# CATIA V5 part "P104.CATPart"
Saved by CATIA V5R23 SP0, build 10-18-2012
Part number: P104
Definition: Tendeur
Bounding box of the stored display mesh (mm): x -4 to 4, y -17 to 17, z -16.952 to 16.952
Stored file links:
  C:\wamp\www\COURS\CONCEPTION GMP1\TITRE 02-SEMESTRE 2\03-TP7-PRESSE MECANIQUE\eleve\P104.CATPart
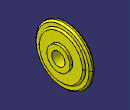
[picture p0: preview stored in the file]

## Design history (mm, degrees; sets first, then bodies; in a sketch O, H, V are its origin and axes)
Body1 (main body)
  Sketch1 on yz-plane, origin (0, 0, 0), H (0, 1, 0), V (0, 0, 1)
    circle A1 centre (0, 0) radius 17
    radius A1 = 17
  Pad1: profile Sketch1, direction (1, 0, 0), length 1.5, mirrored extent
  Chamfer1: length 1, angle 45, on edge [face of Pad1 | face of Pad1] (x2)
  Sketch2 on yz-plane, origin (0, 0, 0), H (0, 1, 0), V (0, 0, 1)
    circle A1 centre (0, 0) radius 14
    radius A1 = 14
  Pad2: profile Sketch2, direction (1, 0, 0), length 2.5, mirrored extent
  Fillet1: radius 1, on edge [face of Pad2 | face of Pad2] (x2)
  Sketch3 on yz-plane, origin (0, 0, 0), H (0, 1, 0), V (0, 0, 1)
    circle A1 centre (0, 0) radius 7
    radius A1 = 7
  Pad3: profile Sketch3, direction (1, 0, 0), length 4, mirrored extent
  Chamfer2: length 1, angle 45, on edge [face of Pad3 | face of Pad3]
  Sketch4 on face of Pad3, origin (4, 0, 0), H (0, 1, 0), V (0, 0, 1)
    point P1 (0, 0)
  Hole1: placed by Sketch4, at (4, 0, 0) direction (-1, 0, 0), diameter 8, depth 10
